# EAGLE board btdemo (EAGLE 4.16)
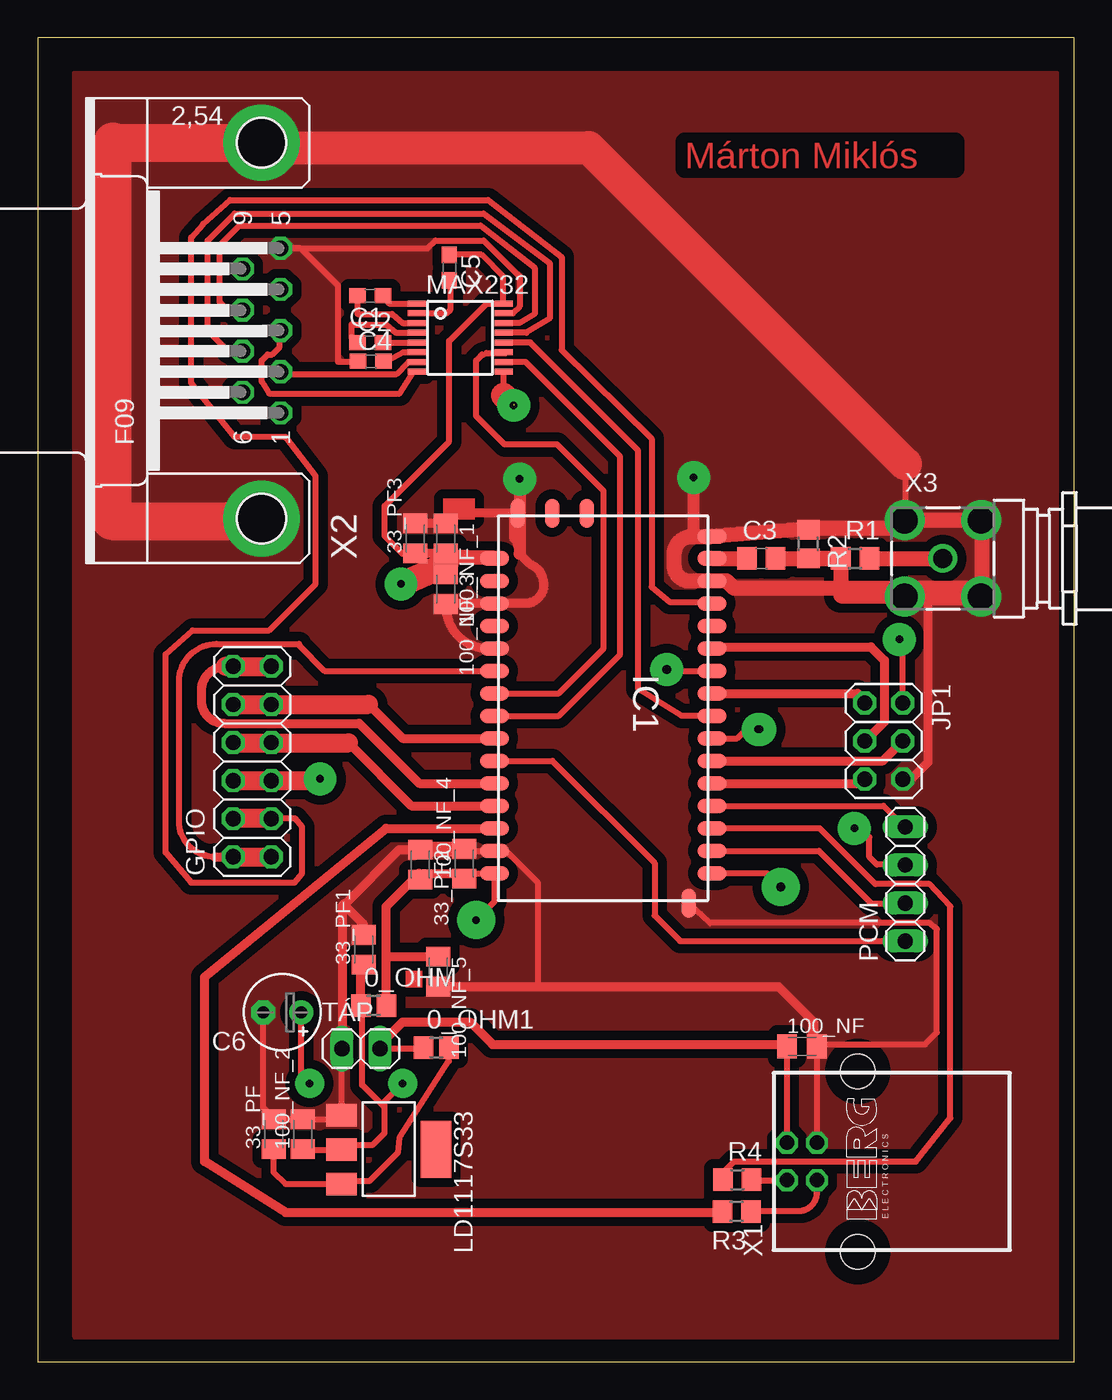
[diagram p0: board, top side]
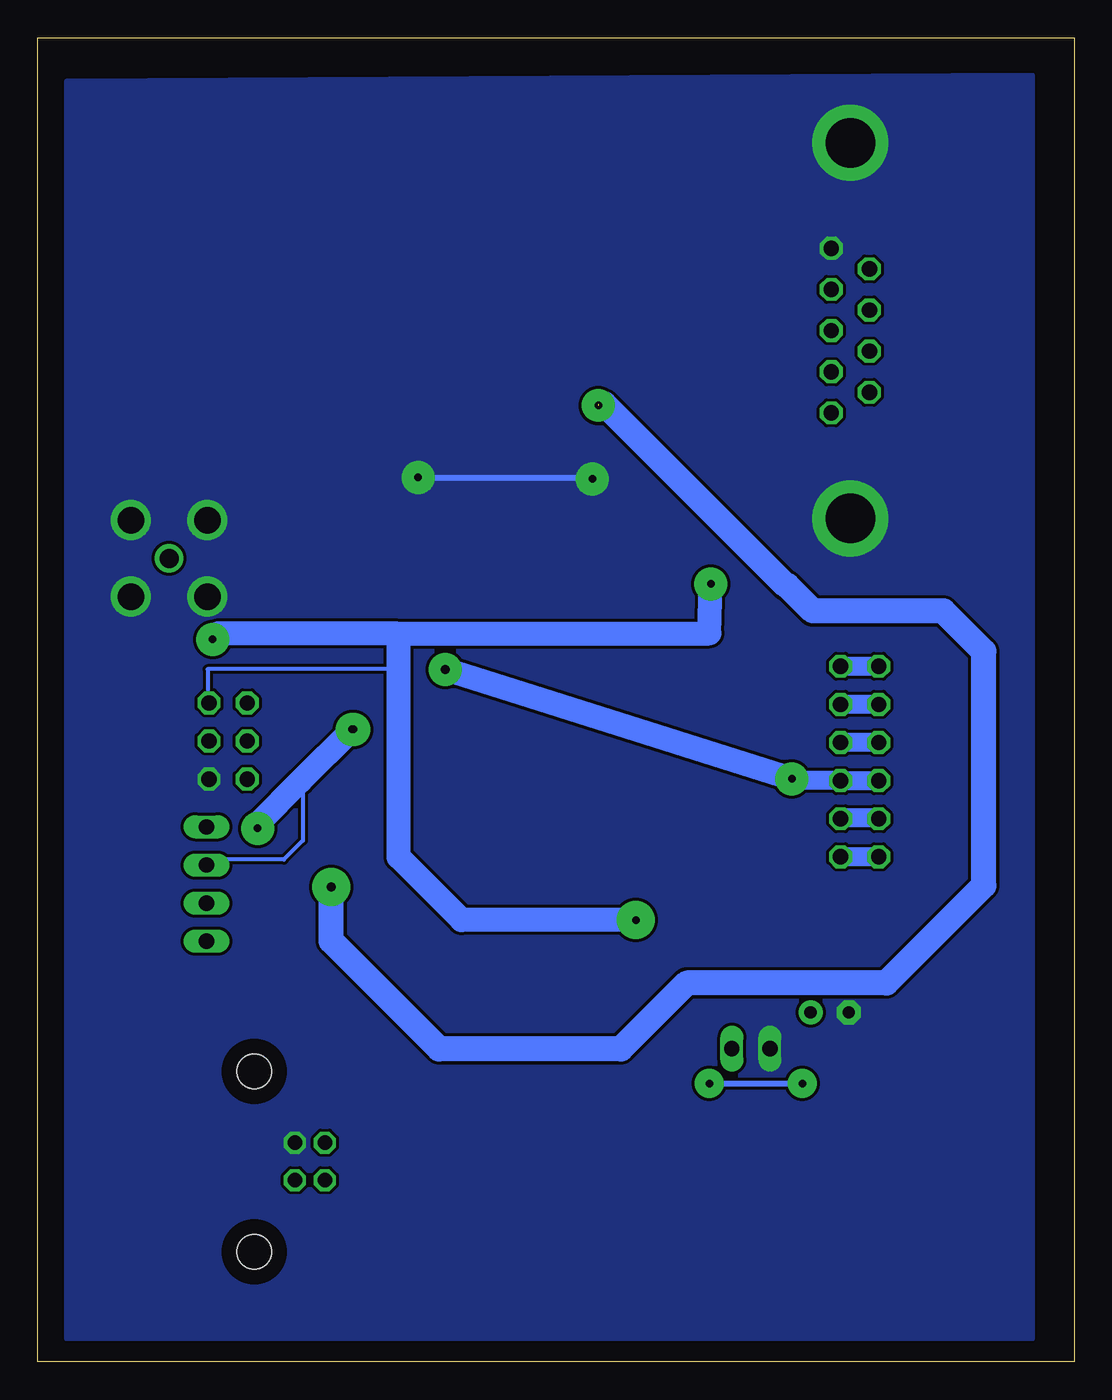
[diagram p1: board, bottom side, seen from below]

Size 69.1 x 88.3 mm. Coordinates in mm from the lower left corner, seen from the top.
Outline: 0,0 69.1,0 69.1,88.3 0,88.3 0,0
Copper layers (1*16): Top 0.035mm / dielectric 1.5mm / Bottom 0.035mm
Design rules "default": minimum track width 10mil, minimum drill 24mil, track to track 8mil, track to pad 8mil, pad to pad 8mil, via to via 8mil, smd to smd 8mil, copper to edge 40mil, drill to drill 8mil, minimum pad ring 10mil, minimum via ring 8mil, stop-mask expansion 4mil, vias tented up to drill 0mil, thermal gap 10mil

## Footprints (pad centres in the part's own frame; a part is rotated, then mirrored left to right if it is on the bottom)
R0805 = smd 1.3 x 1.5: 1 -0.85,0; 2 0.85,0
C0805K = smd 1.3 x 1.6: 1 -1,0; 2 1,0
C0603 = smd 1.1 x 1: 1 -0.85,0; 2 0.85,0
C0805 = smd 1.3 x 1.5: 1 -0.95,0; 2 0.95,0
E2,5-5 = drill 0.813 pad 1.6 round: + -1.27,0 | drill 0.813 pad 1.6 octagon: - 1.27,0
2X06 = drill 1.016 octagon: 1 -6.35,-1.27; 2 -6.35,1.27; 3 -3.81,-1.27; 4 -3.81,1.27; 5 -1.27,-1.27; 6 -1.27,1.27; 7 1.27,-1.27; 8 1.27,1.27; 9 3.81,-1.27; 10 3.81,1.27; 11 6.35,-1.27; 12 6.35,1.27
WRAPTHOR_2022-1 = smd 1.93 x 0.965: 1 -10.5,9; 2 -10.5,7.5; 3 -10.5,6; 4 -10.5,4.5; 5 -10.5,3; 6 -10.5,1.5; 7 -10.5,0; 8 -10.5,-1.5; 9 -10.5,-3; 10 -10.5,-4.5; 11 -10.5,-6; 12 -10.5,-7.5; 13 -10.5,-9; 14 -10.5,-10.5; 15 -10.5,-12; 16 4,-12; 17 4,-10.5; 18 4,-9; 19 4,-7.5; 20 4,-6; 21 4,-4.5; 22 4,-3; 23 4,-1.5; 24 4,0; 25 4,1.5; 26 4,3; 27 4,4.5; 28 4,6; 29 4,7.5; 30 4,9; 31 4,10.45 | smd 0.965 x 1.93: 32 2.45,-14; 33 -8.95,12; 34 -6.65,12; 35 -4.35,12
2X03 = drill 1.016 octagon: 1 -2.54,-1.27; 2 -2.54,1.27; 3 0,-1.27; 4 0,1.27; 5 2.54,-1.27; 6 2.54,1.27
SOT223 = smd 1.499 x 2.007: 1 -2.261,-3.15; 2 0.025,-3.15; 3 2.311,-3.15 | smd 3.81 x 2.007: 4 0,3.15
R-PDSO-G16 = smd 0.4 x 1.2: 1 -2.275,-2.9; 2 -1.625,-2.9; 3 -0.975,-2.9; 4 -0.325,-2.9; 5 0.325,-2.9; 6 0.975,-2.9; 7 1.625,-2.9; 8 2.275,-2.9; 9 2.275,2.9; 10 1.625,2.9; 11 0.975,2.9; 12 0.325,2.9; 13 -0.325,2.9; 14 -0.975,2.9; 15 -1.625,2.9; 16 -2.275,2.9
1X04 = drill 1.016 long: 1 -3.81,0; 2 -1.27,0; 3 1.27,0; 4 3.81,0
R0805' = smd 1.3 x 1.5: 1 -0.95,0; 2 0.95,0
1X02 = drill 1.016 long: 1 -1.27,0; 2 1.27,0
PN61729 = drill 0.95 octagon: 1 1.25,4.71; 2 -1.25,4.71; 3 -1.25,2.71; 4 1.25,2.71 | hole 2.3: -6.02,0; 6.02,0
F09HP = drill 1.016 octagon: 1 -5.486,-1.27; 2 -2.743,-1.27; 3 0,-1.27; 4 2.743,-1.27; 5 5.486,-1.27; 6 -4.115,1.27; 7 -1.372,1.27; 8 1.372,1.27; 9 4.115,1.27 | drill 3.302 pad 5.08 round: G1 -12.522,0; G2 12.522,0
BU-SMA-G = drill 1.27 round: 1 0,0 | drill 1.778 round: 2 -2.55,2.55; 3 2.55,2.55; 4 2.55,-2.55; 5 -2.55,-2.55

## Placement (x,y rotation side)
0_OHM  [R0805]  22.4,23.76 0 top
0_OHM1  [R0805]  26.57,20.96 0 top
33_PF  [C0805K]  15.74,15.19 90 top
33_PF1  [C0805K]  21.73,27.49 90 top
33_PF2  [C0805K]  25.52,33.16 270 top
33_PF3  [C0805K]  25.16,54.9 90 top
100_NF  [C0805K]  50.96,21.04 0 top
100_NF_1  [C0805K]  27.21,54.9 270 top
100_NF_2  [C0805K]  17.69,15.19 90 top
100_NF_3  [C0805K]  27.2,51.53 270 top
100_NF_4  [C0805K]  28.44,33.22 90 top
100_NF_5  [C0805K]  26.69,26.03 270 top
C1  1 uF  [C0603]  22.16,71.08 180 top
C2  1 uF  [C0603]  22.17,67.96 0 top
C3  1 pF  [C0805]  48.24,53.57 0 top
C4  1 uF  [C0603]  22.22,66.71 0 top
C5  1 uF  [C0603]  27.45,72.96 270 top
C6  [E2,5-5]  16.31,23.31 180 top
GPIO  [2X06]  14.31,40.03 90 top
IC1  [WRAPTHOR_2022-1]  40.94,44.58 0 top
JP1  [2X03]  56.4,41.4 270 top
LD1117S33  REG1117  [SOT223]  23.41,14.19 270 top
MAX232  MAX232_TID  [R-PDSO-G16]  28.16,68.29 270 top
PCM  [1X04]  57.83,31.87 90 top
R1  3.3 nH  [R0805']  54.48,53.57 0 top
R2  2.7 nH  [R0805']  51.37,54.54 270 top
R3  [R0805']  46.59,10.04 180 top
R4  [R0805']  46.64,12.15 0 top
TÁP  [1X02]  21.56,20.89 0 top
X1  [PN61729]  54.66,13.37 90 top
X2  [F09HP]  14.93,68.76 90 top
X3  [BU-SMA-G]  60.33,53.57 0 top

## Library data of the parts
0_OHM 0_OHM1 = quantum-sensor
33_PF 33_PF1-33_PF3 100_NF 100_NF_1-100_NF_5 C1-C6 R1-R4 = rcl
GPIO JP1 PCM TÁP = pinhead
IC1 = bluegiga
LD1117S33 = burr-brown
MAX232 = max232ti_n
X1 = con-berg
X2 = con-subd
X3 = con-coax

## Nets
+3V3: 0_OHM.2 33_PF2.2 33_PF3.1 100_NF_1.2 100_NF_3.1 100_NF_4.1 100_NF_5.1 C5.1 IC1.1 IC1.15 JP1.2 MAX232.16
ANT: C3.1 IC1.30
CS: IC1.20 JP1.5
CTS: IC1.8 MAX232.10
D+: R3.1 X1.3
D-: R4.2 X1.2
GND: 33_PF1.2 33_PF2.1 33_PF3.2 33_PF.2 100_NF.2 100_NF_1.1 100_NF_2.2 100_NF_3.2 100_NF_4.2 100_NF_5.2 C4.1 C6.- IC1.3 IC1.5 IC1.14 IC1.29 IC1.31 IC1.32 IC1.33 JP1.6 LD1117S33.1 MAX232.15 R2.1 TÁP.1 X1.4 X2.5 X2.G1 X2.G2 X3.2 X3.3 X3.4 X3.5
MISO: IC1.24 JP1.1
MOSI: IC1.21 JP1.4
N$1: C1.1 MAX232.1
N$2: C2.1 MAX232.4
N$3: C2.2 MAX232.5
N$4: C1.2 MAX232.3
N$5: MAX232.7 X2.2
N$6: MAX232.8 X2.3
N$7: C4.2 MAX232.6
N$8: C5.2 MAX232.2
N$9: IC1.18 R4.1
N$10: MAX232.13 X2.7
N$11: MAX232.14 X2.8
N$12: 0_OHM1.2 33_PF.1 LD1117S33.3
N$13: 0_OHM.1 33_PF1.1 100_NF_2.1 C6.+ LD1117S33.2
N$14: IC1.13 R3.2
N$15: R1.2 X3.1
N$16: C3.2 R1.1 R2.2
PCMC: IC1.22 PCM.3
PCMI: IC1.17 PCM.2
PCMO: IC1.10 PCM.1
PCMS: IC1.19 PCM.4
PIO2: GPIO.1 GPIO.2 IC1.6
PIO3: GPIO.3 GPIO.4 IC1.28
PIO4: GPIO.5 GPIO.6 IC1.25
PIO5: GPIO.7 GPIO.8 IC1.12
PIO6: GPIO.9 GPIO.10 IC1.9
PIO7: GPIO.11 GPIO.12 IC1.11
RTS: IC1.7 MAX232.11
RX: IC1.16 MAX232.9
SCK: IC1.26 JP1.3
TX: IC1.23 MAX232.12
VIN: 0_OHM1.1 100_NF.1 TÁP.2 X1.1

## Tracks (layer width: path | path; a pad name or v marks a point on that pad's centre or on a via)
+3V3  (via drill 0.5 pad 2.18, 0.5 pad 2.54)
  Top 0.406: C5.1 29.59,73.81 31.03,72.37 31.03,70.67 31.13,70.57 31.12,70.56 MAX232.16 29.92,70.56 27.43,68.07 27.43,61.37 23.13,57.07 23.13,55.07 24.33,53.87 25.93,53.87 25.93,53.9 | 28.23,32.47 28.44,32.26 100_NF_4.1 | 28.34,32.58 IC1.15 30.44,30.68 v29.23,29.47 | 28.34,32.58 28.23,32.47 | 25.33,32.27 25.23,32.37 25.33,32.47 | 25.33,32.27 25.44,32.16 33_PF2.2 | 28.23,32.47 25.53,32.47 25.33,32.27 | JP1.2 57.67,47.93 57.43,48.17 | 28.34,32.58 28.34,32.56 28.43,32.47
  Top 0.61: 27.31,53.58 IC1.1 | 27.31,53.58 27.31,53.9 100_NF_1.2 27.1,53.9 27.09,53.89 27.07,53.9 25.93,53.9 33_PF3.1 | 100_NF_3.1 27.21,52.53 27.21,53.58 27.31,53.58 | 28.34,32.58 25.44,32.58 23.23,30.37 23.23,27.07 | 0_OHM.2 23.25,23.95 23.23,23.97 23.23,27.07 | 100_NF_5.1 23.27,27.03 23.23,27.07
  Top 1.016: IC1.1 27.03,53.67 | 100_NF_1.2 27.23,53.97 27.22,53.18
  Top 1.676: v24.23,51.87 27.22,53.18
  Bottom 0.254: JP1.2 57.77,43.65 57.77,46.19 45.03,46.19
  Bottom 0.406: 57.03,48.57 57.63,47.97 | 45.03,48.37 45.23,48.57
  Bottom 1.601: v24.23,51.87 24.33,48.57 45.23,48.57 57.03,48.57 | v29.23,29.47 40.83,29.47 45.03,33.67 45.03,46.19 45.03,48.37
ANT
  Top 1.016: IC1.30 C3.1
CS
  Top 0.61: JP1.5 54.83,38.57 44.83,38.57 44.82,38.58 | 44.82,38.58 44.73,38.67 | IC1.20 44.82,38.58
CTS
  Top 0.406: IC1.8 34.74,43.08 38.83,47.17 38.83,60.37 32.53,66.67 31.33,66.67 31.32,66.66 MAX232.10
D+
  Top 0.406: X1.3 51.95,11.29 arc-90 50.73,10.07 47.73,10.07 arc-90 47.7,10.04 R3.1
D-
  Top 0.406: 47.55,12.15 47.53,12.17 | R4.2 47.55,12.15 | X1.2 47.58,12.12 47.55,12.15
GND  (via drill 0.5 pad 2.18)
  Top 0.406: 51.95,21.27 51.96,21.27 100_NF.2 | 51.95,21.27 X1.4 | 51.95,21.27 51.93,21.27 | 21.07,66.61 21.43,66.67 | C4.1 21.07,66.61 | 21.07,66.61 21.33,66.67 20.03,66.67 20.03,71.77 17.55,74.25 X2.5 26.01,74.25 26.53,74.77 29.73,74.77 32.13,72.37 32.13,70.37 31.67,69.91 MAX232.15 | 28.34,34.08 28.44,34.18 100_NF_4.2 | 28.34,34.08 IC1.14 31.23,34.07 33.33,31.97 33.33,25.03 100_NF_5.2 | 28.34,34.08 28.33,34.07 | 33_PF2.1 25.62,34.16 25.68,34.22 | TÁP.1 20.29,16.51 20.33,16.47 | 20.33,16.47 20.31,16.45 LD1117S33.1 | 20.33,16.47 20.05,16.19 100_NF_2.2 17.81,16.19 | 17.81,16.19 17.83,16.17 | 17.81,16.19 33_PF.2 15.74,16.26 15.04,16.96 C6.- | 51.73,21.17 59.13,21.17 59.93,21.97 59.93,28.87 59.43,29.27 44.83,29.27 43.42,30.58 | 57.83,59.87 57.83,55.37 | X2.G2 14.93,81.17 15.13,80.97 | IC1.33 32.03,56.67 | 33.73,51.67 33.73,52.27 arc90 32.93,53.07 32.13,53.87
  Top 0.61: JP1.6 58.22,38.86 59.33,39.97 59.33,50.97 59.33,51.07 | 31.93,56.58 27.89,56.58 100_NF_1.1 27.11,55.9 27.09,55.88 27.07,55.9 33_PF3.2 | IC1.5 30.02,47.58 arc-90 27.22,50.37 arc-90 27.2,50.4 100_NF_3.2 27.32,50.53 27.32,50.58 IC1.3 32.63,50.57 arc76 33.73,51.67 arc67 33.03,53.07 arc-60 31.93,54.97 | 33_PF2.1 24.12,34.16 20.53,30.57 20.43,30.57 20.33,30.47 20.33,30.37 | 20.29,20.63 20.13,20.47 | TÁP.1 20.29,20.63 | 20.33,30.37 20.33,20.67 20.29,20.63 | 20.33,30.37 20.53,30.37 21.73,29.17 33_PF1.2 | 100_NF_5.2 49.37,25.03 51.63,22.77 | 51.63,22.77 51.73,22.67 51.73,21.17 | 100_NF.2 51.96,21 51.83,20.87 51.73,20.97 51.73,21.17 | 51.63,22.77 51.63,21.27 51.73,21.17 | 43.42,30.58 IC1.32
  Top 0.813: v32.13,58.87 32.13,53.87 | 43.73,55.03 v43.73,58.97
  Top 1.016: 57.98,56.12 X3.3 | 57.98,56.12 57.93,56.17 57.88,56.12 X3.2 57.83,56.07 57.83,55.37 | 57.98,56.12 57.93,56.07 57.93,55.77 57.73,55.57 51.63,55.57 | R2.1 51.45,55.57 51.63,55.57 | 62.93,51.07 X3.4 62.83,50.97 59.33,50.97 57.73,50.97 | X3.3 62.93,56.07 | 57.73,50.97 57.63,50.97 | 57.73,50.97 X3.5 62.93,51.02 62.93,51.67 | IC1.33 31.93,56.58 31.93,54.97 | 25.68,34.22 100_NF_4.2 | IC1.31 43.73,55.03 43.59,55.03 arc90 42.43,53.87 42.43,53.07 arc90 43.43,52.07 44.83,52.07 arc-90 44.84,52.08 IC1.29 45.93,52.07 46.43,51.57 62.73,51.57 62.73,51.67 62.93,51.67 | X3.3 62.93,56.12 62.93,51.67 | 51.63,55.57 45.33,55.07
  Top 2.184: 57.83,59.87 36.73,80.97 15.13,80.97
  Top 2.54: X2.G2 5.12,81.28 5.03,81.37 5.03,56.17 4.93,56.07 14.73,56.07 14.9,56.24 X2.G1
  Bottom 0.406: v32.13,58.87 32.23,58.97 v43.73,58.97
  pour Top (isolate 0.61, no thermals): 2.43,85.87 67.93,85.87 67.93,1.67 2.53,1.67 2.53,85.67
  pour Bottom (no thermals): 2.83,85.77 2.83,1.57 67.13,1.57 67.13,85.37
MISO
  Top 0.61: JP1.1 55.13,44.07 54.63,44.57 IC1.24
MOSI
  Top 0.61: JP1.4 56.33,40.07 44.73,40.07 44.74,40.08 IC1.21
N$1
  Top 0.406: C1.1 23.42,70.58 23.44,70.56 MAX232.1
N$2
  Top 0.406: MAX232.4 23.89,68.61 23.23,69.17 20.93,69.17 20.93,68.27 21.02,68.16 C2.1
N$3
  Top 0.406: 25.32,67.96 25.33,67.97 | 25.32,67.96 MAX232.5 | C2.2 25.32,67.96
N$4
  Top 0.406: C1.2 21.32,69.89 21.33,69.87 23.63,69.87 24.33,69.27 25.23,69.27 25.24,69.26 MAX232.3
N$5
  Top 0.406: MAX232.7 24.72,66.66 23.93,65.87 16.53,65.87 16.38,66.02 X2.2
N$6
  Top 0.406: MAX232.8 25.07,66.01 24.13,64.57 15.43,64.57 14.93,65.37 14.93,66.77 15.33,67.17 15.63,67.17 16.13,67.67 16.13,68.67 16.22,68.76 | 16.22,68.76 16.23,68.77 | 16.22,68.76 X2.3
N$7
  Top 0.406: C4.2 23.29,66.81 23.33,66.77 24.37,67.31 MAX232.6
N$8
  Top 0.406: MAX232.2 27.27,69.91 27.53,70.17 27.53,71.87 27.45,71.95 C5.2
N$9
  Top 0.406: IC1.18 52.12,35.58 55.83,31.87 59.43,31.87 60.83,30.37 60.83,16.27 58.53,13.37 46.43,13.37 45.73,12.67 45.73,12.27 45.83,12.17 45.81,12.15 R4.1
N$10
  Top 0.406: MAX232.13 32.57,68.61 34.13,69.57 34.13,73.27 29.73,76.57 13.13,76.57 11.33,74.77 11.33,68.77 12.73,67.37 13.53,67.37 13.63,67.27 13.66,67.3 X2.7
N$11
  Top 0.406: X2.8 12.67,70.13 12.13,70.67 12.13,74.47 13.43,75.77 29.53,75.77 33.13,72.97 33.13,69.87 32.13,69.27 30.93,69.27 30.94,69.26 MAX232.14
N$12
  Top 0.406: 0_OHM1.2 27.42,20.06 24.13,14.97 24.03,13.97 22.13,12.07 20.33,12.07 20.26,12 LD1117S33.3 20.26,11.84 | 33_PF.1 15.74,12.66 16.53,11.87 20.23,11.87 20.26,11.84 | 20.26,11.84 20.43,11.67
N$13  (via drill 0.5 pad 1.93)
  Top 0.406: 17.62,14.16 17.65,14.19 100_NF_2.1 | 17.62,14.16 LD1117S33.2 20.14,14.16 20.03,14.27 20.23,14.47 22.33,14.47 23.13,15.27 23.13,16.97 | 17.62,14.16 17.53,14.07 | 0_OHM.1 21.63,23.76 21.63,18.47 23.13,16.97 | C6.+ 17.58,19.12 v18.13,18.57 | v24.33,18.57 23.13,17.37 23.13,16.97
  Top 0.61: 33_PF1.1 21.73,26.27 21.55,26.09 0_OHM.1
  Bottom 0.406: v24.33,18.57 v18.13,18.57
N$14
  Top 0.61: IC1.13 23.24,35.58 11.13,25.67 11.13,13.37 16.53,9.97 45.43,9.97 45.53,10.07 45.56,10.04 R3.2
N$15
  Top 1.016: R1.2 X3.1
N$16
  Top 1.016: C3.2 R1.1 | R1.1 53.53,51.07 57.83,51.07 | R1.1 53.63,53.57 | R2.2 51.37,53.57 R1.1
N$17
  Bottom 1.27: 13.03,46.37 15.53,46.37
N$18  (via drill 0.5 pad 2.18)
  other vias: 57.43,48.17
N$20
  Bottom 1.27: 12.93,36.27 15.53,36.27
N$22
  Bottom 1.27: 15.63,33.67 13.13,33.67 13.13,33.77
N$24  (via drill 0.5 pad 2.18)
  other vias: 31.73,63.77
N$25  (via drill 0.5 pad 2.54)
  other vias: 29.23,29.47
N$26  (via drill 0.5 pad 2.18)
  other vias: 54.43,35.57
N$27  (via drill 0.5 pad 2.18)
  other vias: 48.03,42.17
PCMC  (via drill 0.5 pad 2.18)
  Top 0.406: IC1.22 46.63,41.57 47.23,42.17 v48.13,42.17 | PCM.3 57.8,33.17 55.93,33.17 55.43,33.67 55.43,34.97 54.83,35.57 54.33,35.57
  Bottom 0.254: PCM.3 56.5,33.49 52.69,33.49 51.42,34.76 51.42,38.57 51.58,38.73
  Bottom 0.406: 54.43,35.87 54.43,35.67
  Bottom 1.601: v48.13,42.17 51.58,38.73 54.43,35.87
PCMI
  Top 0.406: IC1.17 52.07,34.08 55.56,30.59 57.85,30.59 57.86,30.6 | 57.86,30.6 57.91,30.65 | 57.86,30.6 PCM.2
PCMO
  Top 0.406: IC1.10 34.32,40.08 41.13,33.27 41.13,29.77 42.83,28.07 57.93,28.07 57.94,28.06 | 57.94,28.06 58.03,27.97 | 57.94,28.06 PCM.1
PCMS
  Top 0.406: PCM.4 57.83,35.65 57.82,35.64 56.38,37.08 IC1.19
PIO2
  Top 0.406: IC1.6 19.12,46.08 17.43,47.77 17.43,47.87 11.93,47.87 arc90 9.43,45.37 9.43,36.07 arc90 11.83,33.67
  Top 0.61: GPIO.2 12.93,33.67 | GPIO.2 arc90 GPIO.2 | GPIO.2 13.13,33.67 11.83,33.67 | GPIO.1 arc90 GPIO.1 arc-90 GPIO.1
  Top 1.27: 13.13,33.67 GPIO.1
PIO3
  Top 0.406: GPIO.3 17.18,36.22 17.63,35.67 17.63,32.57 17.13,31.97 10.23,31.97 8.53,33.97 8.53,47.17 10.33,48.77 15.43,48.77 18.53,51.87 18.53,59.07 16.53,61.67 13.13,61.67 10.23,65.27 10.23,74.97 11.03,75.87 12.83,77.47 30.03,77.47 34.93,73.67 34.93,67.47 40.93,61.57 40.93,51.67 42.13,50.67 44.53,50.67 44.62,50.58 IC1.28 | 15.68,36.22 arc-90 15.73,36.17 arc90 15.68,36.22
  Top 1.27: GPIO.4 GPIO.3 15.68,36.22
PIO4  (via drill 0.5 pad 2.18, 0.6 pad 2.18)
  Top 0.406: 18.72,38.76 v18.83,38.87 | IC1.25 42.02,46.08 41.98,46.12 | v41.93,46.17 41.98,46.12 | v41.93,46.17 41.83,46.27 41.93,46.27 | 41.98,46.12 41.93,46.07 arc215 v41.93,46.17 | GPIO.6 arc90 GPIO.6
  Top 1.27: GPIO.6 GPIO.5 18.72,38.76
  Bottom 0.254: 15.86,38.77 15.86,38.57 GPIO.5
  Bottom 1.27: GPIO.6 15.86,38.77 18.73,38.77 18.73,38.87
  Bottom 1.601: v18.83,38.87 v41.93,46.17
PIO5
  Top 0.61: IC1.12 24.92,37.08 20.73,41.27 | 13.03,41.27 13.04,41.28 GPIO.8
  Top 1.27: 13.03,41.27 20.73,41.27
  Bottom 0.406: GPIO.8 13.03,41.27
  Bottom 1.27: GPIO.8 GPIO.7
PIO6
  Top 0.61: 22.06,43.84 24.33,41.57 30.53,41.57 30.52,41.58 IC1.9
  Top 1.27: GPIO.10 22.06,43.84
  Bottom 0.406: GPIO.9 15.63,43.84 15.63,43.87
  Bottom 1.27: GPIO.10 15.63,43.84
PIO7
  Top 0.61: GPIO.11 GPIO.12 | GPIO.11 15.62,46.38 15.63,46.37 | GPIO.11 | 12.53,46.37 arc90 10.93,44.77 10.93,44.07 arc90 12.43,42.57 21.43,42.57 25.43,38.57 IC1.11
  Top 1.27: 12.53,46.37 GPIO.11
RTS
  Top 0.406: IC1.7 34.74,44.58 37.73,47.57 37.73,58.07 34.63,61.17 31.13,61.17 29.23,63.07 29.23,66.77 29.53,67.07 | 29.53,67.07 29.63,67.17 | 29.53,67.07 29.93,67.27 31.23,67.27 31.09,67.31 MAX232.11
RX  (via drill 0.6 pad 2.54)  (1 unrouted)
  Top 0.406: 31.06,64.44 MAX232.9 | IC1.16 48.62,32.58 v49.53,31.67
  Top 1.676: 31.73,63.77 31.06,64.44
  Bottom 0.406: 19.13,51.77 19.23,51.77 | 31.33,63.87 31.73,63.87 31.83,63.77
  Bottom 1.676: v49.53,31.67 49.53,28.07 42.33,20.87 30.23,20.87 25.83,25.27 12.53,25.27 6.03,31.77 6.03,47.37 8.73,50.07 17.43,50.07 19.13,51.77 | 19.23,51.77 31.33,63.87
SCK
  Top 0.61: JP1.3 55.13,41.37 56.43,42.67 56.43,46.77 55.53,47.67 45.03,47.67 IC1.26
TX
  Top 0.406: MAX232.12 32.84,67.96 40.03,60.77 40.03,44.87 42.93,43.07 44.63,43.07 44.64,43.08 IC1.23
VIN
  Top 0.406: 100_NF.1 49.96,21.14 arc90 49.93,21.17 arc-90 49.95,21.15 X1.1 | 0_OHM1.1 25.65,20.89 TÁP.2
  Top 0.61: 49.93,21.17 30.33,21.17 28.83,22.67 24.33,22.67 22.73,21.07 22.83,20.97 TÁP.2
(copper drawn outside any net)
  shapes: Top area x2

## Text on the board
Top: Márton Miklós
_tPlace: 2,54 | 9 | 5 | F09 | 6 | 1 | IC1 | IC1 | E L E C T R O N I C S
_tNames: C5 | MAX232 | C1 | C2 | C4 | X3 | 100_NF_1 | R2 | C3 | R1 | X2 | 33_PF3 | 100_NF_3 | JP1 | 33_PF2 | GPIO | 100_NF_4 | 100_NF_5 | 33_PF1 | PCM | 0_OHM | C6 | TÁP | 0_OHM1 | 100_NF | LD1117S33 | 33_PF | 100_NF_2 | R4 | R3 | X1
203bmp: /usr/share/eagle/ulp/cam2print-box-grey-optimize.bmp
